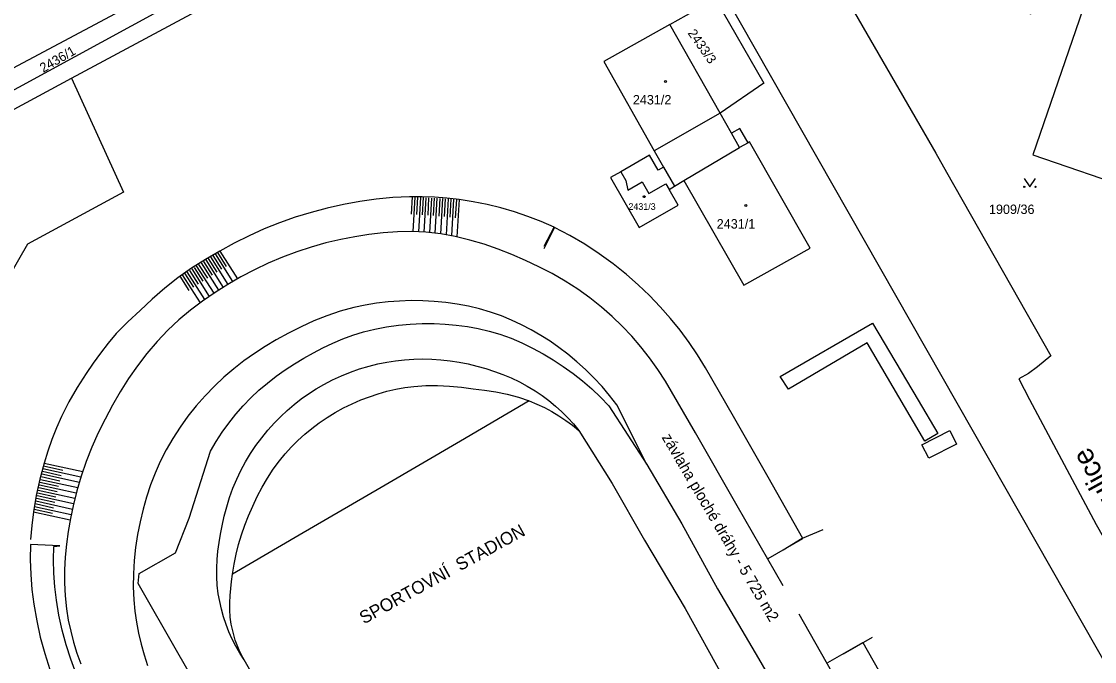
# Model space of a CAD drawing. Extents: x -483721 to -481876, y -1129170 to -1127366.
# Drawn here: x -482470.6 to -482277, y -1128126.6 to -1128011.1 of the extents above; entities that cross this region are included whole.
import ezdxf

# ---------------------------------------------------------------- set-up
doc = ezdxf.new("R2010")
doc.units = 0
for name, color, linetype in [('1 Terenni Hrany', 7, 'Continuous'), ('2 Ploty', 7, 'Continuous'), ('3 Betonove Plochy', 7, 'Continuous'), ('3 Budovy', 7, 'Continuous'), ('4 Komunikace', 7, 'Continuous'), ('4 Obrubniky', 7, 'Continuous'), ('Hranice parcel', 7, 'Continuous'), ('Parcelní čísla', 7, 'Continuous'), ('u_návrh_popis', 7, 'Continuous'), ('u_sil_popis', 7, 'Continuous'), ('Vnitřní kresba', 7, 'Continuous'), ('x_rozpiska', 7, 'Continuous'), ('Značky budov', 7, 'Continuous'), ('Značky kultur', 7, 'Continuous')]:
    doc.layers.add(name, color=color, linetype=linetype)

msp = doc.modelspace()

# ---------------------------------------------------------------- linework, layer by layer
at = {"layer": '1 Terenni Hrany'}
for points in [[(-482400.09, -1128042.75), (-482400.27, -1128045.88)], [(-482399.59, -1128042.78), (-482399.95, -1128049.02)], [(-482399.09, -1128042.8), (-482399.27, -1128045.93)], [(-482398.59, -1128042.83), (-482398.95, -1128049.07)], [(-482398.09, -1128042.86), (-482398.27, -1128045.98)], [(-482397.6, -1128042.89), (-482397.95, -1128049.12)], [(-482397.1, -1128042.92), (-482397.27, -1128046.03)], [(-482396.6, -1128042.95), (-482396.95, -1128049.2)], [(-482396.1, -1128042.97), (-482396.28, -1128046.12)], [(-482395.6, -1128043), (-482395.96, -1128049.32)], [(-482395.1, -1128043.03), (-482395.28, -1128046.2)], [(-482394.6, -1128043.06), (-482394.96, -1128049.43)], [(-482394.1, -1128043.09), (-482394.28, -1128046.3)], [(-482393.6, -1128043.12), (-482393.97, -1128049.6)], [(-482393.1, -1128043.14), (-482393.29, -1128046.42)], [(-482392.6, -1128043.17), (-482392.98, -1128049.78)], [(-482392.1, -1128043.2), (-482392.29, -1128046.53)], [(-482391.6, -1128043.23), (-482391.99, -1128049.98)], [(-482435.63, -1128053.05), (-482432.46, -1128058.04)], [(-482435.21, -1128052.79), (-482433.62, -1128055.29)], [(-482434.79, -1128052.52), (-482431.59, -1128057.54)], [(-482438.59, -1128054.93), (-482437.01, -1128057.4)], [(-482438.16, -1128054.66), (-482435.02, -1128059.61)], [(-482437.74, -1128054.4), (-482436.17, -1128056.87)], [(-482437.32, -1128054.13), (-482434.17, -1128059.08)], [(-482436.9, -1128053.86), (-482435.32, -1128056.33)], [(-482436.48, -1128053.59), (-482433.32, -1128058.54)], [(-482436.06, -1128053.32), (-482434.47, -1128055.81)], [(-482441.54, -1128056.81), (-482438.32, -1128061.87)], [(-482441.12, -1128056.54), (-482439.52, -1128059.06)], [(-482440.7, -1128056.28), (-482437.51, -1128061.28)], [(-482440.27, -1128056.01), (-482438.68, -1128058.5)], [(-482439.85, -1128055.74), (-482436.68, -1128060.72)], [(-482439.43, -1128055.47), (-482437.85, -1128057.95)], [(-482439.01, -1128055.2), (-482435.86, -1128060.15)], [(-482441.96, -1128057.08), (-482440.34, -1128059.63)], [(-482466.67, -1128091.79), (-482459.82, -1128093.3)], [(-482466.56, -1128091.3), (-482463.11, -1128092.06)], [(-482466.45, -1128090.81), (-482459.5, -1128092.35)], [(-482467.1, -1128093.74), (-482460.4, -1128095.22)], [(-482466.99, -1128093.25), (-482463.62, -1128094)], [(-482466.88, -1128092.76), (-482460.11, -1128094.26)], [(-482466.77, -1128092.28), (-482463.37, -1128093.03)], [(-482467.53, -1128095.69), (-482460.9, -1128097.16)], [(-482467.42, -1128095.21), (-482464.1, -1128095.94)], [(-482467.31, -1128094.72), (-482460.66, -1128096.19)], [(-482467.21, -1128094.23), (-482463.87, -1128094.97)], [(-482467.96, -1128097.65), (-482461.36, -1128099.11)], [(-482467.85, -1128097.16), (-482464.56, -1128097.89)], [(-482467.75, -1128096.67), (-482461.14, -1128098.13)], [(-482467.64, -1128096.18), (-482464.33, -1128096.91)], [(-482468.39, -1128099.6), (-482461.76, -1128101.07)], [(-482468.29, -1128099.11), (-482464.97, -1128099.84)], [(-482468.18, -1128098.62), (-482461.56, -1128100.09)], [(-482468.07, -1128098.13), (-482464.77, -1128098.87)]]:
    msp.add_lwpolyline(points, dxfattribs=at)
at = {"layer": '2 Ploty'}
for points in [[(-482376.24, -1128051.63), (-482374.47, -1128048.22), (-482376.81, -1128047.19), (-482379.2, -1128046.27), (-482381.62, -1128045.45), (-482384.08, -1128044.73), (-482386.56, -1128044.12), (-482389.08, -1128043.62), (-482391.6, -1128043.23), (-482393.83, -1128042.97), (-482396.06, -1128042.81), (-482398.3, -1128042.72), (-482400.53, -1128042.72), (-482403.54, -1128042.87), (-482406.54, -1128043.18), (-482409.52, -1128043.6), (-482412.48, -1128044.13), (-482415.41, -1128044.78), (-482418.32, -1128045.54), (-482421.18, -1128046.42), (-482424, -1128047.42), (-482426.78, -1128048.53), (-482429.5, -1128049.75), (-482432.17, -1128051.09), (-482434.79, -1128052.52), (-482437.37, -1128054.02), (-482439.91, -1128055.61), (-482442.35, -1128057.33), (-482444.7, -1128059.21), (-482446.95, -1128061.2), (-482449.15, -1128063.24), (-482451.35, -1128065.28), (-482453.46, -1128067.42), (-482454.93, -1128069.14), (-482456.3, -1128070.93), (-482457.61, -1128072.78), (-482458.87, -1128074.66), (-482460.48, -1128077.17), (-482462, -1128079.74), (-482463.36, -1128082.39), (-482464.26, -1128084.44), (-482465.07, -1128086.54), (-482465.79, -1128088.67), (-482466.45, -1128090.81), (-482467.23, -1128093.72), (-482467.89, -1128096.66), (-482468.4, -1128099.62), (-482468.71, -1128102.1), (-482468.93, -1128104.58)], [(-482325.98, -1128102.85), (-482329.71, -1128104.41), (-482333.13, -1128106.5)], [(-482317.11, -1128122.28), (-482322.34, -1128125.3)]]:
    msp.add_lwpolyline(points, dxfattribs=at)
at = {"layer": '3 Betonove Plochy'}
for points in [[(-482335.84, -1128108.06), (-482329.6, -1128104.41), (-482335.84, -1128093.34), (-482342.14, -1128082.37), (-482347.14, -1128073.61), (-482348.58, -1128071.28), (-482350.11, -1128069.02), (-482351.74, -1128066.83), (-482353.46, -1128064.7), (-482355.31, -1128062.59), (-482357.26, -1128060.57), (-482359.29, -1128058.63), (-482361.4, -1128056.78), (-482363.83, -1128054.83), (-482366.35, -1128053), (-482368.95, -1128051.3), (-482371.64, -1128049.71), (-482374.39, -1128048.26), (-482376.34, -1128052.11)], [(-482460.68, -1128128.83), (-482461.64, -1128126.23), (-482462.48, -1128123.61), (-482463.2, -1128120.95), (-482463.79, -1128118.26), (-482464.23, -1128115.54), (-482464.52, -1128113.13), (-482464.69, -1128110.71), (-482464.76, -1128108.28), (-482464.72, -1128105.85), (-482463.63, -1128105.72), (-482468.95, -1128105.5), (-482468.97, -1128108.2), (-482468.87, -1128110.91), (-482468.66, -1128113.61), (-482468.32, -1128116.29), (-482467.81, -1128119.29), (-482467.16, -1128122.26), (-482466.35, -1128125.2), (-482465.41, -1128128.09)], [(-482325.12, -1128126.82), (-482318.79, -1128123.2), (-482312.89, -1128133.61), (-482306.96, -1128144.09), (-482300.81, -1128154.85), (-482299.38, -1128157.61), (-482298.08, -1128160.45), (-482296.92, -1128163.34), (-482295.9, -1128166.29), (-482295.11, -1128168.95), (-482294.45, -1128171.65), (-482293.9, -1128174.37), (-482293.46, -1128177.12), (-482293.14, -1128179.88), (-482292.94, -1128182.54), (-482292.84, -1128185.21), (-482292.85, -1128187.88), (-482292.96, -1128190.54), (-482299.89, -1128190.33)]]:
    msp.add_lwpolyline(points, dxfattribs=at)
at = {"layer": '3 Budovy'}
for points in [[(-482305.26, -1128085.47), (-482307.61, -1128086.84), (-482317.98, -1128069.12), (-482332.2, -1128077.48), (-482333.67, -1128075.2), (-482317.05, -1128065.52), (-482308.77, -1128079.47), (-482305.26, -1128085.47)], [(-482303.1, -1128084.93), (-482301.86, -1128087.37), (-482306.9, -1128089.94), (-482308.16, -1128087.51), (-482303.1, -1128084.93)]]:
    msp.add_lwpolyline(points, dxfattribs=at)
at = {"layer": '4 Komunikace'}
for points in [[(-482333.17, -1128112.95), (-482341.45, -1128098.54), (-482348.97, -1128085.34), (-482354.4, -1128076.01), (-482355.77, -1128073.88), (-482357.24, -1128071.82), (-482358.8, -1128069.83), (-482360.45, -1128067.91), (-482362.19, -1128066.08), (-482364.01, -1128064.32), (-482365.91, -1128062.65), (-482368.02, -1128060.97), (-482370.22, -1128059.41), (-482372.48, -1128057.95), (-482374.82, -1128056.6), (-482377.2, -1128055.35), (-482379.64, -1128054.2), (-482382.09, -1128053.14), (-482384.58, -1128052.16), (-482387.11, -1128051.28), (-482389.68, -1128050.53), (-482392.29, -1128049.9), (-482394.92, -1128049.43), (-482397.59, -1128049.13), (-482400.16, -1128049.01), (-482402.74, -1128049.05), (-482405.31, -1128049.23), (-482407.87, -1128049.53), (-482410.42, -1128049.93), (-482412.95, -1128050.42), (-482415.63, -1128051.05), (-482418.29, -1128051.79), (-482420.91, -1128052.65), (-482423.49, -1128053.62), (-482426.03, -1128054.71), (-482428.52, -1128055.89), (-482430.96, -1128057.18), (-482433.32, -1128058.54), (-482435.63, -1128059.99), (-482437.88, -1128061.54), (-482440.06, -1128063.19), (-482442.15, -1128064.94), (-482444.15, -1128066.8), (-482446.1, -1128068.84), (-482447.93, -1128070.99), (-482449.64, -1128073.23), (-482451.24, -1128075.55), (-482452.74, -1128077.93), (-482454.15, -1128080.37), (-482455.47, -1128082.86), (-482456.7, -1128085.37), (-482457.83, -1128087.92), (-482458.86, -1128090.52), (-482459.78, -1128093.16), (-482460.58, -1128095.83), (-482461.24, -1128098.55), (-482461.71, -1128100.83), (-482462.12, -1128103.13), (-482462.44, -1128105.45), (-482462.67, -1128107.77), (-482462.8, -1128110.11), (-482462.81, -1128112.45), (-482462.69, -1128114.78), (-482462.43, -1128117.11), (-482462.1, -1128119.14), (-482461.67, -1128121.16), (-482461.15, -1128123.16), (-482460.54, -1128125.13), (-482459.85, -1128127.07)], [(-482357.76, -1128091.06), (-482363.16, -1128080.3), (-482364.46, -1128078.62), (-482365.83, -1128076.99), (-482367.28, -1128075.43), (-482368.79, -1128073.93), (-482370.37, -1128072.51), (-482372.01, -1128071.15), (-482373.59, -1128069.95), (-482375.21, -1128068.81), (-482376.87, -1128067.74), (-482378.58, -1128066.75), (-482380.33, -1128065.82), (-482382.13, -1128064.99), (-482383.96, -1128064.24), (-482385.92, -1128063.56), (-482387.92, -1128062.98), (-482389.93, -1128062.5), (-482391.97, -1128062.11), (-482394.03, -1128061.82), (-482396.09, -1128061.62), (-482398.16, -1128061.5), (-482400.26, -1128061.47), (-482402.35, -1128061.54), (-482404.43, -1128061.7), (-482406.51, -1128061.95), (-482408.57, -1128062.3), (-482410.62, -1128062.74), (-482413.06, -1128063.4), (-482415.46, -1128064.2), (-482417.81, -1128065.13), (-482420.11, -1128066.18), (-482422.37, -1128067.32), (-482424.58, -1128068.54), (-482426.58, -1128069.74), (-482428.53, -1128071.01), (-482430.43, -1128072.36), (-482432.27, -1128073.79), (-482434.04, -1128075.3), (-482435.74, -1128076.9), (-482437.42, -1128078.64), (-482439.02, -1128080.46), (-482440.54, -1128082.35), (-482441.95, -1128084.31), (-482443.27, -1128086.34), (-482444.47, -1128088.44), (-482445.51, -1128090.5), (-482446.44, -1128092.6), (-482447.26, -1128094.75), (-482447.98, -1128096.94), (-482448.61, -1128099.15), (-482449.14, -1128101.39), (-482449.6, -1128103.72), (-482449.96, -1128106.06), (-482450.22, -1128108.42), (-482450.36, -1128110.78), (-482450.38, -1128113.15), (-482450.27, -1128115.52), (-482450.08, -1128117.53), (-482449.8, -1128119.53), (-482449.43, -1128121.52), (-482448.98, -1128123.48), (-482448.44, -1128125.43), (-482447.82, -1128127.35)], [(-482442.74, -1128107.02), (-482440.33, -1128100.75), (-482436.43, -1128088.68), (-482435.42, -1128086.93), (-482434.32, -1128085.23), (-482433.14, -1128083.59), (-482431.89, -1128082), (-482430.56, -1128080.48), (-482429.16, -1128079.02), (-482427.71, -1128077.64), (-482426.19, -1128076.35), (-482424.61, -1128075.13), (-482422.98, -1128073.97), (-482421.31, -1128072.88), (-482419.6, -1128071.85), (-482417.89, -1128070.88), (-482416.16, -1128069.98), (-482414.39, -1128069.14), (-482412.58, -1128068.38), (-482410.75, -1128067.7), (-482408.87, -1128067.12), (-482406.79, -1128066.6), (-482404.69, -1128066.19), (-482402.56, -1128065.89), (-482400.42, -1128065.7), (-482398.28, -1128065.61), (-482396.13, -1128065.61), (-482394.12, -1128065.71), (-482392.12, -1128065.88), (-482390.12, -1128066.15), (-482388.14, -1128066.51), (-482386.18, -1128066.97), (-482384.24, -1128067.53), (-482382.23, -1128068.26), (-482380.27, -1128069.1), (-482378.35, -1128070.04), (-482376.47, -1128071.07), (-482374.64, -1128072.17), (-482372.81, -1128073.36), (-482371.04, -1128074.64), (-482369.33, -1128075.98), (-482367.68, -1128077.4), (-482366.09, -1128078.89), (-482364.57, -1128080.45), (-482357.76, -1128091.06), (-482351.46, -1128101.77), (-482345.01, -1128113.49), (-482337.58, -1128126.06), (-482330.59, -1128138.24)], [(-482430.41, -1128126.34), (-482431.18, -1128125.13), (-482431.89, -1128123.88), (-482432.53, -1128122.6), (-482433.12, -1128121.29), (-482433.64, -1128119.95), (-482434.09, -1128118.59), (-482434.48, -1128117.2), (-482434.8, -1128115.81), (-482435.05, -1128114.39), (-482435.23, -1128112.86), (-482435.32, -1128111.32), (-482435.32, -1128109.78), (-482435.25, -1128108.24), (-482435.11, -1128106.7), (-482434.9, -1128105.17), (-482434.65, -1128103.65), (-482434.36, -1128102.14), (-482433.98, -1128100.42), (-482433.52, -1128098.71), (-482433, -1128097.02), (-482432.4, -1128095.36), (-482431.73, -1128093.72), (-482430.97, -1128092.13), (-482430.13, -1128090.58), (-482429.23, -1128089.08), (-482428.25, -1128087.62), (-482427.2, -1128086.22), (-482426.09, -1128084.86), (-482424.92, -1128083.55), (-482423.78, -1128082.39), (-482422.6, -1128081.29), (-482421.36, -1128080.23), (-482420.08, -1128079.23), (-482418.76, -1128078.29), (-482417.4, -1128077.41), (-482416, -1128076.59), (-482414.44, -1128075.77), (-482412.84, -1128075.03), (-482411.21, -1128074.37), (-482409.55, -1128073.79), (-482407.86, -1128073.28), (-482406.28, -1128072.89), (-482404.67, -1128072.57), (-482403.06, -1128072.32), (-482401.43, -1128072.15), (-482399.8, -1128072.05), (-482398.17, -1128072.01), (-482396.53, -1128072.04), (-482394.89, -1128072.15), (-482393.25, -1128072.33), (-482391.61, -1128072.57), (-482390, -1128072.89), (-482388.39, -1128073.28), (-482386.8, -1128073.73), (-482385.25, -1128074.24), (-482383.72, -1128074.8), (-482382.22, -1128075.43), (-482380.74, -1128076.13), (-482379.31, -1128076.9), (-482377.91, -1128077.75), (-482376.64, -1128078.61), (-482375.41, -1128079.53), (-482374.23, -1128080.5), (-482373.09, -1128081.53), (-482372.01, -1128082.61), (-482370.97, -1128083.74), (-482369.99, -1128084.92)], [(-482322.32, -1128132.12), (-482330.27, -1128118.08)]]:
    msp.add_lwpolyline(points, dxfattribs=at)
at = {"layer": '4 Obrubniky'}
for points in [[(-482424.01, -1128137.47), (-482430.41, -1128126.34), (-482430.86, -1128125.47), (-482431.28, -1128124.58), (-482431.65, -1128123.67), (-482431.98, -1128122.75), (-482432.27, -1128121.81), (-482432.51, -1128120.86), (-482432.71, -1128119.9), (-482432.9, -1128118.61), (-482432.99, -1128117.32), (-482432.99, -1128116.02), (-482432.93, -1128114.73), (-482432.81, -1128113.44), (-482432.67, -1128112.16), (-482432.5, -1128110.88), (-482432.21, -1128109.07), (-482431.83, -1128107.28), (-482431.38, -1128105.51), (-482430.85, -1128103.76), (-482430.25, -1128102.03), (-482429.59, -1128100.32), (-482428.84, -1128098.57), (-482428.03, -1128096.85), (-482427.16, -1128095.16), (-482426.2, -1128093.52), (-482425.15, -1128091.92), (-482424.02, -1128090.39), (-482422.96, -1128089.12), (-482421.84, -1128087.9), (-482420.67, -1128086.72), (-482419.45, -1128085.61), (-482418.17, -1128084.55), (-482416.85, -1128083.55), (-482415.43, -1128082.58), (-482413.96, -1128081.68), (-482412.44, -1128080.85), (-482410.89, -1128080.09), (-482409.31, -1128079.4), (-482407.77, -1128078.82), (-482406.21, -1128078.3), (-482404.63, -1128077.85), (-482403.03, -1128077.48), (-482401.41, -1128077.18), (-482399.78, -1128076.96), (-482397.63, -1128076.8), (-482395.48, -1128076.8), (-482393.33, -1128076.92), (-482391.19, -1128077.12), (-482389.06, -1128077.38), (-482387.01, -1128077.65), (-482384.96, -1128077.97), (-482382.93, -1128078.37), (-482380.92, -1128078.89), (-482378.96, -1128079.56), (-482377.58, -1128080.14), (-482376.22, -1128080.79), (-482374.9, -1128081.49), (-482373.62, -1128082.26), (-482372.37, -1128083.09), (-482371.16, -1128083.97), (-482369.99, -1128084.92)], [(-482378.96, -1128079.56), (-482391.36, -1128086.83), (-482405.69, -1128095.21), (-482420.45, -1128103.83), (-482432.5, -1128110.88)], [(-482369.99, -1128084.92), (-482364.02, -1128094.47), (-482358.17, -1128104.74), (-482350.84, -1128117.09), (-482343.92, -1128129.57)], [(-482378.5, -1128219.74), (-482385.02, -1128223.59), (-482386.04, -1128223.22), (-482391.54, -1128213.62), (-482397.54, -1128203.16), (-482403.07, -1128193.53), (-482414.79, -1128173.07), (-482417.7, -1128168.01), (-482428.2, -1128149.82), (-482430.6, -1128145.47), (-482436.13, -1128135.85), (-482442.34, -1128125.05), (-482449.49, -1128112.57), (-482449.33, -1128110.75), (-482442.74, -1128107.02)]]:
    msp.add_lwpolyline(points, dxfattribs=at)
at = {"layer": 'Hranice parcel'}
for p, q in [((-482367.87, -1127963.92), (-482526.05, -1128048.26)), ((-482344.54, -1128027.63), (-482353.6, -1128011.59)), ((-482344.54, -1128027.63), (-482356.4, -1128034.44))]:
    msp.add_line(p, q, dxfattribs=at)
for points in [[(-482286.79, -1127956.55), (-482287.8, -1127959.57), (-482296.54, -1127984.93), (-482298.01, -1127989.31), (-482295.34, -1128007.4), (-482292.28, -1128008.42), (-482288.47, -1128009.67), (-482283.87, -1127996.64), (-482275.84, -1127999.4), (-482288.12, -1128035.12), (-482269.53, -1128041.52), (-482266.9, -1128033.86), (-482266.32, -1128032.16), (-482259.05, -1128010.98), (-482231.12, -1128022.34)], [(-482529.31, -1128054.66), (-482527.89, -1128053.89), (-482525.35, -1128052.5), (-482366.67, -1127966.02)], [(-482345.11, -1127966.35), (-482338.74, -1127977.4), (-482305.64, -1128034.82), (-482303.71, -1128038.3), (-482284.85, -1128071.44), (-482287.27, -1128073.4), (-482288.88, -1128074.62), (-482290.67, -1128075.58), (-482288.73, -1128079.35), (-482276.7, -1128101.91), (-482267.12, -1128118.74)], [(-482461.52, -1128021.31), (-482398.25, -1127987.31), (-482366.53, -1127969.89), (-482364.93, -1127969.05)], [(-482364.93, -1127969.05), (-482343.84, -1128006.04), (-482234.22, -1128198.65), (-482215.31, -1128236.66), (-482200.01, -1128286.72)], [(-482353.6, -1128011.59), (-482347.58, -1128008.22), (-482345.33, -1128006.97), (-482336.61, -1128022.18), (-482344.54, -1128027.63)], [(-482353.6, -1128011.59), (-482365.53, -1128018.31), (-482356.4, -1128034.44)], [(-482527.94, -1128056.76), (-482523.14, -1128053.94), (-482505.49, -1128045.11), (-482488.96, -1128036.14), (-482461.52, -1128021.31)], [(-482461.52, -1128021.31), (-482452.12, -1128041.9), (-482469.48, -1128051.27), (-482482.08, -1128073.17), (-482482.57, -1128075.09)], [(-482353.69, -1128041.38), (-482352.78, -1128040.82), (-482351.08, -1128039.76), (-482340.27, -1128058.68), (-482328.31, -1128052.03), (-482339.23, -1128032.81), (-482339.49, -1128032.96), (-482340.98, -1128030.37), (-482342.5, -1128031.24), (-482344.54, -1128027.63)], [(-482356.4, -1128034.44), (-482354.73, -1128037.39), (-482355.69, -1128037.94), (-482357.24, -1128035.23), (-482362.43, -1128038.19)], [(-482362.43, -1128038.19), (-482364.28, -1128039.24), (-482359.15, -1128048.25), (-482352.1, -1128044.21), (-482353.69, -1128041.38)], [(-482362.43, -1128038.19), (-482361.52, -1128039.8), (-482361.2, -1128041.52), (-482358.58, -1128040.03), (-482357.37, -1128042.14), (-482354.29, -1128040.38), (-482353.69, -1128041.38)]]:
    msp.add_lwpolyline(points, dxfattribs=at)
at = {"layer": 'Vnitřní kresba'}
for p, q in [((-482341.04, -1128033.83), (-482342.5, -1128031.24)), ((-482339.49, -1128032.96), (-482341.04, -1128033.83)), ((-482351.08, -1128039.76), (-482341.04, -1128033.83)), ((-482354.73, -1128037.39), (-482352.78, -1128040.82))]:
    msp.add_line(p, q, dxfattribs=at)
at = {"layer": 'Značky budov'}
for centre in [(-482354.39, -1128021.9), (-482358.21, -1128042.7), (-482339.88, -1128044.31)]:
    msp.add_circle(centre, 0.175, dxfattribs=at)
at = {"layer": 'Značky kultur'}
msp.add_lwpolyline([(-482289.65, -1128039.42), (-482288.65, -1128040.92), (-482287.65, -1128039.42)], dxfattribs=at)
for centre in [(-482289.65, -1128040.92), (-482287.65, -1128040.92)]:
    msp.add_circle(centre, 0.1, dxfattribs=at)

# ---------------------------------------------------------------- texts
at = {"layer": 'Parcelní čísla'}
for s, rotation, p in [('2433/3', 305, (-482350.44, -1128013.18)), ('2436/1', 30, (-482466.63, -1128020.36))]:
    msp.add_text(s, height=1.7, rotation=rotation, dxfattribs=at).set_placement(p)
for s, height, p in [('2431/2', 1.7, (-482360.27, -1128026.05)), ('2431/3', 1.2, (-482361.06, -1128045.08)), ('1909/36', 1.7, (-482296.03, -1128045.83)), ('2431/1', 1.7, (-482345.14, -1128048.46))]:
    msp.add_text(s, height=height, dxfattribs=at).set_placement(p)
at = {"layer": 'u_návrh_popis'}
msp.add_text('závlaha ploché dráhy - 5 725 m2', height=2, rotation=300.3333, dxfattribs=at).set_placement((-482355.12, -1128086.15))
at = {"layer": 'u_sil_popis'}
msp.add_text('Husova ulice', height=3.75, rotation=118.9729, dxfattribs=at).set_placement((-482264.09, -1128112.78))
at = {"layer": 'x_rozpiska'}
msp.add_text('SPORTOVNÍ  STADION', height=2.3, rotation=28.9559, dxfattribs=at).set_placement((-482408.78, -1128119.95))

doc.saveas('drawing.dxf')
